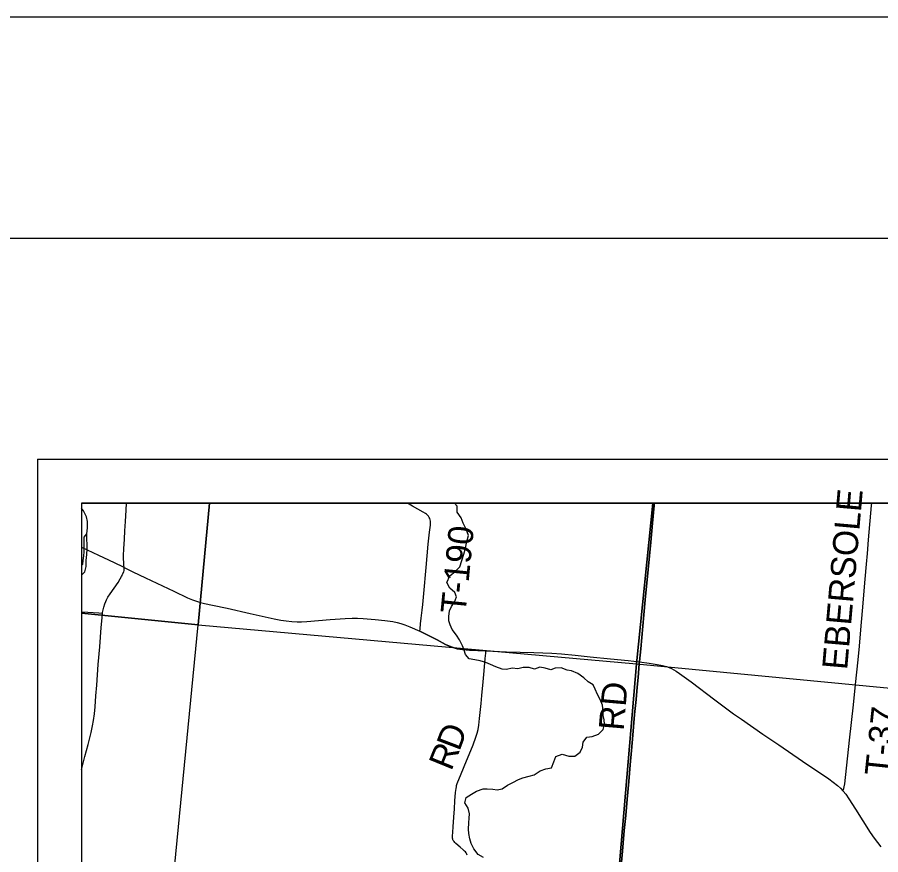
# Model space of a CAD drawing. Extents: x 0 to 34, y 0 to 22.
# Drawn here: x 1.954 to 3.909, y 20.104 to 22 of the extents above; entities that cross this region are included whole.
import ezdxf

# ---------------------------------------------------------------- set-up
doc = ezdxf.new("R2010")
doc.units = 0
for name, color, linetype in [('Default', 7, 'Continuous'), ('GM_X_City_Street', 7, 'Continuous'), ('GM_X_County_Road', 7, 'Continuous'), ('GM_X_County_Road_Text', 7, 'Continuous'), ('GM_X_Minor_Lake', 7, 'Continuous'), ('GM_X_Minor_River', 7, 'Continuous'), ('GM_X_Section', 7, 'Continuous'), ('GM_X_Township_Road', 7, 'Continuous'), ('GM_X_Township_Road_Text', 7, 'Continuous'), ('SH_Border', 7, 'Continuous'), ('SH_Cut_Line', 7, 'Continuous'), ('SH_Data', 7, 'Continuous')]:
    doc.layers.add(name, color=color, linetype=linetype)

msp = doc.modelspace()

# ---------------------------------------------------------------- linework, layer by layer
at = {"layer": 'Default'}
for points in [[(2.3893, 20.9), (2.1, 20.9), (2.1, 20.6507), (2.3636, 20.6247)], [(3.3925, 20.9), (2.3893, 20.9), (2.3636, 20.6247), (3.3559, 20.5363)], [(4.3798, 20.9), (3.3925, 20.9), (3.3559, 20.5363), (4.3405, 20.4419)], [(2.1, 20.6507), (2.1, 19.6357), (2.2658, 19.6175), (2.3636, 20.6247)]]:
    msp.add_lwpolyline(points, close=True, dxfattribs=at)
at = {"layer": 'GM_X_City_Street'}
for points in [[(3.3189, 20.0537), (3.324, 20.1125), (3.3282, 20.1589), (3.3313, 20.1929), (3.3346, 20.23), (3.3382, 20.2702), (3.3415, 20.3074), (3.3436, 20.3321), (3.3467, 20.3661), (3.3491, 20.394), (3.3515, 20.4218), (3.3547, 20.4558), (3.3573, 20.4836), (3.3595, 20.5053), (3.3621, 20.5362), (3.3626, 20.5415), (3.3656, 20.5702), (3.3725, 20.6475), (3.3757, 20.6815), (3.3822, 20.7495), (3.3881, 20.8114), (3.3921, 20.8547), (3.3957, 20.8949), (3.3961, 20.9), (2.1, 20.9), (2.1, 19.6388)], [(8.7795, 20.9), (3.3961, 20.9), (3.3957, 20.8949), (3.3921, 20.8547), (3.3881, 20.8114), (3.3822, 20.7495), (3.3757, 20.6815), (3.3725, 20.6475), (3.3656, 20.5702), (3.3626, 20.5415), (3.3621, 20.5362), (3.3595, 20.5053), (3.3573, 20.4836), (3.3547, 20.4558), (3.3515, 20.4218), (3.3491, 20.394), (3.3467, 20.3661), (3.3436, 20.3321), (3.3415, 20.3074), (3.3382, 20.2702), (3.3346, 20.23), (3.3313, 20.1929), (3.3282, 20.1589), (3.324, 20.1125), (3.3189, 20.0537)]]:
    msp.add_lwpolyline(points, dxfattribs=at)
at = {"layer": 'GM_X_County_Road'}
for points in [[(2.1962, 20.7545), (2.1958, 20.7603), (2.1952, 20.767), (2.1949, 20.7724), (2.1949, 20.7817), (2.1954, 20.7969), (2.1966, 20.8188), (2.1976, 20.8377), (2.1989, 20.8589), (2.2004, 20.8841), (2.2012, 20.9)], [(3.3629, 20.541), (3.3658, 20.5696), (3.3727, 20.647), (3.3759, 20.681), (3.3824, 20.749), (3.3883, 20.8108), (3.3924, 20.8541), (3.3959, 20.8944), (3.3964, 20.9)], [(2.1, 20.8002), (2.1127, 20.7943), (2.138, 20.7824), (2.1605, 20.7719), (2.1912, 20.7571), (2.1962, 20.7545)], [(2.1473, 20.6509), (2.1475, 20.6524), (2.1485, 20.6584), (2.15, 20.6645), (2.1524, 20.672), (2.1546, 20.6773), (2.1565, 20.6815), (2.1595, 20.687), (2.1645, 20.6948), (2.1735, 20.7074), (2.1823, 20.7203), (2.1871, 20.7284), (2.1899, 20.7338), (2.1913, 20.7366), (2.1927, 20.7395), (2.1951, 20.7447), (2.1961, 20.7478), (2.1964, 20.7509), (2.1962, 20.7545)], [(2.1962, 20.7545), (2.2021, 20.7513), (2.216, 20.7444), (2.2441, 20.7311), (2.3087, 20.7006), (2.3396, 20.686), (2.3511, 20.6811), (2.3599, 20.6779), (2.3688, 20.6752), (2.3779, 20.6729), (2.3962, 20.6691), (2.4296, 20.6621), (2.481, 20.6502), (2.5083, 20.6441), (2.5356, 20.6381), (2.5509, 20.6351), (2.5632, 20.6334), (2.5756, 20.6321), (2.5881, 20.6314), (2.5974, 20.6315), (2.6099, 20.6321), (2.6625, 20.6364), (2.6966, 20.6391), (2.7121, 20.6398), (2.7244, 20.6398), (2.7368, 20.6392), (2.7646, 20.6366), (2.7862, 20.6343), (2.8046, 20.6318), (2.8138, 20.6302), (2.8227, 20.6278), (2.8314, 20.6247), (2.8428, 20.6199), (2.8655, 20.6099)], [(2.1, 20.2966), (2.1075, 20.3263), (2.1144, 20.3534), (2.1213, 20.3805), (2.1247, 20.3957), (2.1269, 20.4079), (2.129, 20.4234), (2.1305, 20.4389), (2.1322, 20.4637), (2.1341, 20.4884), (2.1375, 20.5349), (2.1409, 20.5751), (2.1441, 20.6185), (2.1461, 20.6401), (2.1473, 20.6509)], [(2.8655, 20.6099), (2.8878, 20.5991), (2.9043, 20.5905), (2.9236, 20.5804), (2.9322, 20.5765), (2.9409, 20.5732), (2.9499, 20.5705), (2.9561, 20.5692), (2.9623, 20.5684), (2.9778, 20.5671), (3.0149, 20.5654)], [(3.0149, 20.5654), (3.0616, 20.5638), (3.0927, 20.5628), (3.1237, 20.5618), (3.164, 20.5602), (3.1857, 20.5586), (3.2166, 20.5557), (3.2506, 20.5523), (3.2969, 20.5479), (3.3371, 20.5439), (3.3629, 20.541)], [(3.3114, 19.9558), (3.3144, 19.9944), (3.3173, 20.0315), (3.3191, 20.0532), (3.3242, 20.112), (3.3284, 20.1583), (3.3315, 20.1924), (3.3348, 20.2295), (3.3385, 20.2697), (3.3417, 20.3068), (3.3439, 20.3316), (3.3469, 20.3656), (3.3493, 20.3934), (3.3517, 20.4213), (3.3549, 20.4553), (3.3576, 20.4831), (3.3597, 20.5047), (3.3623, 20.5357), (3.3629, 20.541)], [(3.3629, 20.541), (3.3843, 20.538), (3.4027, 20.5351), (3.4148, 20.5326), (3.4237, 20.5302), (3.4295, 20.5282), (3.4352, 20.5258), (3.4406, 20.5229), (3.4458, 20.5197), (3.4534, 20.5143), (3.4791, 20.4953), (3.5332, 20.4551), (3.5755, 20.4235), (3.5932, 20.4108), (3.6419, 20.3774), (3.6778, 20.3529), (3.7317, 20.3161), (3.7908, 20.276), (3.8009, 20.2688), (3.8105, 20.261), (3.8173, 20.2548), (3.8228, 20.2489)], [(3.8228, 20.2489), (3.8237, 20.2481), (3.8294, 20.2409), (3.8364, 20.2307), (3.8514, 20.2071), (3.8848, 20.1547), (3.8936, 20.1418), (3.9011, 20.1318), (3.9091, 20.1223)]]:
    msp.add_lwpolyline(points, dxfattribs=at)
at = {"layer": 'GM_X_Minor_Lake'}
for points in [[(2.1, 20.7591), (2.1028, 20.762), (2.1037, 20.7704), (2.105, 20.7806), (2.1054, 20.7897), (2.1058, 20.8144), (2.1055, 20.8231), (2.1117, 20.8306)], [(2.1, 20.7374), (2.1072, 20.7449), (2.1104, 20.757), (2.1105, 20.7703), (2.1115, 20.7839), (2.1124, 20.7965), (2.1125, 20.8063), (2.1119, 20.8189), (2.1117, 20.8306)]]:
    msp.add_lwpolyline(points, dxfattribs=at)
at = {"layer": 'GM_X_Minor_River'}
for points in [[(3.2624, 20.479), (3.2575, 20.4886), (3.2466, 20.4959), (3.2369, 20.5044), (3.2233, 20.5144), (3.2086, 20.5207), (3.1991, 20.5219), (3.1855, 20.527), (3.1714, 20.5264), (3.1619, 20.5227), (3.1494, 20.5267), (3.1373, 20.5291), (3.125, 20.524), (3.1126, 20.5279), (3.0996, 20.5281), (3.0874, 20.5248), (3.0746, 20.5268), (3.0612, 20.5236), (3.0517, 20.5245), (3.0377, 20.5296), (3.0253, 20.5347), (3.0147, 20.5397), (3.0018, 20.5433), (2.9897, 20.545), (2.9772, 20.5478), (2.969, 20.5574), (2.966, 20.5669), (2.9616, 20.5768), (2.9549, 20.591), (2.9486, 20.6009), (2.9389, 20.6143), (2.9337, 20.6243), (2.9312, 20.6338), (2.9309, 20.6433), (2.9326, 20.6562), (2.9369, 20.666), (2.9435, 20.6758), (2.9482, 20.6883), (2.9449, 20.6978), (2.9332, 20.7078), (2.9265, 20.7208), (2.9336, 20.7355), (2.9458, 20.746), (2.9558, 20.7558), (2.9606, 20.7701), (2.9653, 20.7849), (2.9685, 20.7982), (2.9717, 20.8133), (2.9757, 20.8269), (2.9706, 20.8414), (2.9631, 20.8544), (2.9591, 20.867), (2.9498, 20.88), (2.9499, 20.8933), (2.9437, 20.9)], [(2.1, 20.7374), (2.1072, 20.7449), (2.1104, 20.757), (2.1105, 20.7703), (2.1115, 20.7839), (2.1124, 20.7965), (2.1125, 20.8063), (2.1119, 20.8189), (2.1117, 20.8306), (2.113, 20.8443), (2.1131, 20.8587), (2.111, 20.8694), (2.1043, 20.8824), (2.1, 20.8884)], [(3.0096, 20.0977), (2.9971, 20.105), (2.9878, 20.1173), (2.9815, 20.1295), (2.9786, 20.1398), (2.9765, 20.1524), (2.9758, 20.1619), (2.976, 20.1763), (2.9773, 20.1866), (2.9778, 20.1968), (2.9749, 20.2094), (2.9675, 20.2216), (2.9703, 20.2334), (2.9825, 20.2416), (2.9936, 20.2483), (3.0085, 20.253), (3.018, 20.2537), (3.0309, 20.2524), (3.0404, 20.2508), (3.0514, 20.2537), (3.064, 20.2615), (3.0755, 20.2674), (3.0885, 20.2745), (3.0984, 20.2785), (3.1125, 20.2822), (3.1244, 20.2854), (3.1374, 20.294), (3.1507, 20.2988), (3.1633, 20.3009), (3.1688, 20.3145), (3.1735, 20.3266), (3.1876, 20.3322), (3.2024, 20.3274), (3.216, 20.3276), (3.2279, 20.3362), (3.2334, 20.3479), (3.2354, 20.3589), (3.2432, 20.3702), (3.2557, 20.372), (3.2695, 20.3771), (3.2802, 20.3876), (3.2834, 20.4001), (3.2828, 20.4096), (3.2806, 20.4195), (3.2804, 20.4294), (3.279, 20.4427), (3.2735, 20.4557), (3.2675, 20.4668), (3.2624, 20.479)]]:
    msp.add_lwpolyline(points, dxfattribs=at)
at = {"layer": 'GM_X_Section'}
for points in [[(2.3636, 20.6247), (3.3559, 20.5363), (3.2703, 19.5334), (2.2658, 19.6175)], [(3.3559, 20.5363), (4.3405, 20.4419), (4.2088, 19.4458), (3.2703, 19.5334)]]:
    msp.add_lwpolyline(points, close=True, dxfattribs=at)
at = {"layer": 'GM_X_Township_Road'}
for points in [[(2.8655, 20.6099), (2.866, 20.6152), (2.8672, 20.6268), (2.8685, 20.6396), (2.8705, 20.6581), (2.8718, 20.6709), (2.8744, 20.6957), (2.8798, 20.7544), (2.8846, 20.8069), (2.8874, 20.8347), (2.8892, 20.8501), (2.8895, 20.8562), (2.8893, 20.8593), (2.8888, 20.8623), (2.8879, 20.8651), (2.8866, 20.8679), (2.885, 20.8704), (2.883, 20.8727), (2.8808, 20.8748), (2.8784, 20.8766), (2.8732, 20.8799), (2.8486, 20.8932), (2.8371, 20.9)], [(3.8228, 20.2489), (3.8239, 20.2519), (3.8248, 20.2543), (3.8257, 20.2575), (3.827, 20.2644), (3.838, 20.3632), (3.8425, 20.4033), (3.8468, 20.4434), (3.8517, 20.4897), (3.8572, 20.5453), (3.8601, 20.5762), (3.8633, 20.6133), (3.8669, 20.6566), (3.8733, 20.7277), (3.8763, 20.7617), (3.8783, 20.7864), (3.8808, 20.8174), (3.8876, 20.8947), (3.888, 20.9)], [(2.1, 20.6544), (2.1136, 20.6532), (2.1386, 20.6515), (2.1473, 20.6509)], [(3.0149, 20.5654), (2.9778, 20.5671), (2.9623, 20.5684), (2.9561, 20.5692), (2.9499, 20.5705), (2.9409, 20.5732), (2.9322, 20.5765), (2.9236, 20.5804), (2.9043, 20.5905), (2.8878, 20.5991), (2.8655, 20.6099)], [(2.9724, 20.1035), (2.9716, 20.1057), (2.97, 20.1084), (2.9685, 20.1104), (2.9666, 20.1124), (2.9635, 20.1152), (2.9566, 20.1214), (2.9471, 20.1295), (2.9449, 20.1317), (2.9427, 20.134), (2.9411, 20.1367), (2.9404, 20.1382), (2.94, 20.1397), (2.9396, 20.1413), (2.9395, 20.1428), (2.9394, 20.146), (2.9398, 20.1554), (2.9407, 20.1677), (2.9422, 20.1894), (2.9436, 20.2079), (2.9448, 20.2265), (2.9463, 20.2451), (2.9475, 20.2544), (2.9481, 20.2579), (2.9486, 20.2606), (2.9499, 20.2651), (2.9514, 20.2693), (2.9573, 20.2839), (2.9656, 20.304), (2.9857, 20.3527), (2.9922, 20.3701), (2.9951, 20.379), (2.9972, 20.388), (2.9987, 20.3971), (3.0007, 20.4125), (3.0039, 20.4465), (3.0056, 20.465), (3.0084, 20.4959), (3.0107, 20.5206), (3.0134, 20.5484), (3.0145, 20.5607), (3.0149, 20.5654)]]:
    msp.add_lwpolyline(points, dxfattribs=at)
at = {"layer": 'SH_Border'}
msp.add_lwpolyline([(1.5, 21.5), (33.5, 21.5), (33.5, 0.5), (1.5, 0.5)], close=True, dxfattribs=at)
at = {"layer": 'SH_Cut_Line'}
msp.add_lwpolyline([(0, 0), (34, 0), (34, 22), (0, 22)], close=True, dxfattribs=at)
at = {"layer": 'SH_Data'}
for p, q in [((2, 21), (9, 21)), ((2, 21), (2, 14)), ((2.1, 20.9), (2.1, 14.1)), ((2.1, 20.9), (8.9, 20.9))]:
    msp.add_line(p, q, dxfattribs=at)

# ---------------------------------------------------------------- texts
at = {"layer": 'GM_X_County_Road_Text'}
msp.add_text('RD', height=0.05682, rotation=85.0773, dxfattribs=at).set_placement((3.3266, 20.3838))
at = {"layer": 'GM_X_Township_Road_Text'}
for s, height, rotation, p in [('EBERSOLE', 0.05682, 85.0128, (3.8324, 20.5214)), ('T-190', 0.05682, 84.4015, (2.9687, 20.6483)), ('T-37', 0.05682, 84.0115, (3.9286, 20.2808)), ('D', 0.0568, 69.2528, (2.9547, 20.3367)), ('R', 0.0568, 67.8029, (2.9365, 20.292))]:
    msp.add_text(s, height=height, rotation=rotation, dxfattribs=at).set_placement(p)

doc.saveas('drawing.dxf')
